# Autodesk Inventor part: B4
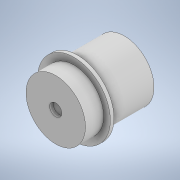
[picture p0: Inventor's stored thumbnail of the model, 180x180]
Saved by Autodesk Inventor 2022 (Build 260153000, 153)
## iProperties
Created: 2024-12
Part Number: B4
Material: 一般
Document SubType Name: Modeling
Designer: jsat7
Density: 1 g/cm^3
Appearance: 既定
Author: jsat7
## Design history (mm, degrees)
sketch "スケッチ1"
  geometry: C1 r 2.45 at (0, 0); 1 further point
  constraints: 1 centre point, 1 coincident
  dimensions: "d0" = 4.9 diameter of C1
extrude "押し出し1" new body sketch "スケッチ1" distance "d1" = 1.5; taper "d2" = 0 deg
sketch "スケッチ2"
  geometry: C1 r 3 at (0, 0); 1 further point
  constraints: 1 centre point, 1 coincident
  dimensions: "d3" = 6 diameter of C1
extrude "押し出し2" join sketch "スケッチ2" distance "d4" = 0.3; taper "d5" = 0 deg
sketch "スケッチ3"
  geometry: C1 r 2.45 at (0, 0); 1 further point
  constraints: 1 centre point, 1 coincident
  dimensions: "d6" = 4.9 diameter of C1
extrude "押し出し3" join sketch "スケッチ3" distance "d7" = 3.85; taper "d8" = 0 deg
sketch "スケッチ4"
  geometry: C1 r 1.5 at (0, 0); 1 further point
  constraints: 1 centre point, 1 coincident
  dimensions: "d9" = 3 diameter of C1
extrude "押し出し4" cut sketch "スケッチ4" distance "d10" = 3.5; taper "d11" = 0 deg
sketch "スケッチ5"
  geometry: C1 r 0.5 at (0, 0); 1 further point
  constraints: 1 centre point, 1 coincident
  dimensions: "d12" = 1 diameter of C1
extrude "押し出し5" cut sketch "スケッチ5" distance "d13" = 0.3; taper "d14" = 0 deg
node "ソリッド1"
